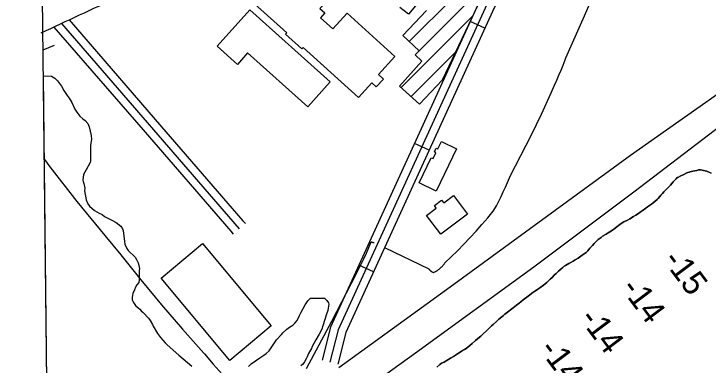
# Model space of a CAD drawing. Extents: x 3683613 to 3738215, y 469626 to 495384.
# Drawn here: x 3687652 to 3688948, y 487753 to 488409 of the extents above; entities that cross this region are included whole.
import ezdxf

# ---------------------------------------------------------------- set-up
doc = ezdxf.new("R2010")
doc.units = 0
for name, color, linetype in [('V-BLDG-OTLN', 7, 'Continuous'), ('V-GRID-FRAM', 7, 'Continuous'), ('V-LEVE-TOET', 7, 'Continuous'), ('V-ROAD-CNTR', 7, 'Continuous'), ('V-SITE-VEGE', 7, 'Continuous'), ('V-TOPO-SHOR', 7, 'Continuous'), ('V-TOPO-SPOT', 7, 'Continuous')]:
    doc.layers.add(name, color=color, linetype=linetype)

msp = doc.modelspace()

# ---------------------------------------------------------------- linework, layer by layer
at = {"layer": 'V-BLDG-OTLN'}
for p, q in [((3688390.1, 488357.4), (3688562.9, 488530.2)), ((3688408.3, 488340.2), (3688516.6, 488448.5)), ((3688374.8, 488271.4), (3688507.9, 488404.5)), ((3688393.3, 488254.6), (3688475.9, 488337.1))]:
    msp.add_line(p, q, dxfattribs=at)
for points in [[(3688363.3, 488329.6), (3688332.6, 488295.6), (3688341.7, 488287.3), (3688328.5, 488272.7), (3688320.2, 488280.2), (3688295.4, 488252.7), (3688191.8, 488346.2), (3688189.6, 488343.8), (3688159.2, 488371.3), (3688161.2, 488373.6), (3688101.1, 488427.8), (3688142.8, 488474), (3688151.4, 488466.2), (3688172.7, 488489.8), (3688235.8, 488432.8), (3688223.3, 488418.9), (3688232.2, 488410.9), (3688224, 488401.8), (3688247.3, 488380.8), (3688273.9, 488410.3)], [(3688242.3, 488282.4), (3688200.5, 488235.6), (3688088, 488336.1), (3688069, 488314.8), (3688031.3, 488348.5), (3688092.2, 488416.6)], [(3688440.3, 488078.3), (3688408.5, 488093.5), (3688431.1, 488140.6), (3688434.6, 488138.9), (3688439.9, 488149.8), (3688436.9, 488151.2), (3688440.4, 488158.3), (3688443.5, 488156.8), (3688450.2, 488170.7), (3688478.2, 488157.3)], [(3688448.9, 487997.6), (3688422.2, 488032.8), (3688440.4, 488046.6), (3688437, 488051.1), (3688450.4, 488061.2), (3688454.3, 488056.1), (3688472.5, 488069.9), (3688498.7, 488035.4)], [(3688004, 487980.1), (3688132.2, 487826.5), (3688054.7, 487761.8), (3687926.5, 487915.4)]]:
    msp.add_lwpolyline(points, close=True, dxfattribs=at)
for points in [[(3688525, 488440.4), (3688451.2, 488285.1), (3688409.2, 488240.2), (3688371.8, 488274.1), (3688413.7, 488320.5), (3688401, 488332.3), (3688408.3, 488340.1), (3688378.3, 488368.6), (3688422.4, 488415.2)], [(3688410.8, 488435.7), (3688388.7, 488408.7), (3688372.4, 488420.9)]]:
    msp.add_lwpolyline(points, dxfattribs=at)
at = {"layer": 'V-GRID-FRAM'}
msp.add_lwpolyline([(3687651.7, 493221.8), (3719350.3, 493590.7), (3719569.8, 475409.4), (3687855.3, 475040.3), (3687651.7, 493221.8)], dxfattribs=at)
at = {"layer": 'V-LEVE-TOET'}
for points in [[(3688258.5, 487748.9), (3688466.2, 487899.4), (3688803.1, 488145.2), (3689067.6, 488331.3)], [(3688996.3, 488218.7), (3688809.7, 488076.2), (3688622.7, 487936.2), (3688401.7, 487775.6), (3688274.9, 487684)]]:
    msp.add_lwpolyline(points, dxfattribs=at)
at = {"layer": 'V-ROAD-CNTR'}
for p, q in [((3688531.1, 488382.1), (3688503.8, 488394.6)), ((3688427.2, 488154.7), (3688399.9, 488167.2)), ((3688323.3, 487927.3), (3688296.1, 487939.8))]:
    msp.add_line(p, q, dxfattribs=at)
for points in [[(3688751.7, 488885.9), (3688531.8, 488419.8), (3688257.4, 487819.1), (3688242, 487759)], [(3688731.8, 488878.8), (3688518.2, 488426.1), (3688243.2, 487824.1), (3688227.5, 487762.7)], [(3688758.9, 488866), (3688545.4, 488413.5), (3688271.6, 487814.1), (3688256.5, 487755.3)], [(3687740.7, 488391), (3688072.7, 488007.7)], [(3687754.8, 488397.6), (3687915.7, 488211.9)], [(3687726.5, 488384.5), (3687893, 488192.3)], [(3687915.7, 488211.9), (3688079.4, 488022.9)], [(3687893, 488192.3), (3688056.7, 488003.3)], [(3688079.4, 488022.9), (3688084.1, 488017.6)], [(3688056.7, 488003.3), (3688061.4, 487997.9)]]:
    msp.add_lwpolyline(points, dxfattribs=at)
msp.add_spline([(3687702.9, 488373.5), (3687846.1, 488439.9), (3688068.4, 488539.2), (3688266.3, 488645.5), (3688507.8, 488813.9), (3688673, 488939.5)], degree=3, dxfattribs=at)
at = {"layer": 'V-SITE-VEGE'}
for p, q in [((3687706.9, 488292.7), (3687710.2, 488293.3)), ((3687714.7, 487596.9), (3687706.9, 488292.7)), ((3687710.2, 488293.3), (3687722.1, 488292.5)), ((3687722.1, 488292.5), (3687728.3, 488288.9)), ((3687728.3, 488288.9), (3687732.9, 488284.3)), ((3687732.9, 488284.3), (3687740.6, 488273.9)), ((3687740.6, 488273.9), (3687745.1, 488266.1)), ((3687745.1, 488266.1), (3687750.9, 488256.4)), ((3687750.9, 488256.4), (3687754.9, 488251.7)), ((3687754.9, 488251.7), (3687759.6, 488243.9)), ((3687759.6, 488243.9), (3687765.8, 488231.3)), ((3687765.8, 488231.3), (3687769.4, 488225.3)), ((3687769.4, 488225.3), (3687775, 488218.2)), ((3687775, 488218.2), (3687780.7, 488213.1)), ((3687780.7, 488213.1), (3687785, 488210)), ((3687785, 488210), (3687789.6, 488204.5)), ((3687789.6, 488204.5), (3687792.2, 488197.9)), ((3687792.2, 488197.9), (3687796.3, 488182.3)), ((3687796.3, 488182.3), (3687796.4, 488174.4)), ((3687795.1, 488167.4), (3687794.7, 488163.2)), ((3687795.9, 488171.5), (3687795.1, 488167.4)), ((3687796.4, 488174.4), (3687795.9, 488171.5)), ((3687794.7, 488163.2), (3687795, 488138.6)), ((3687794, 488131.8), (3687786.9, 488117.8)), ((3687794.6, 488134.2), (3687794, 488131.8)), ((3687795, 488138.6), (3687794.6, 488134.2)), ((3687786.9, 488117.8), (3687783.9, 488113.4)), ((3687781.8, 488108.9), (3687780.6, 488098.7)), ((3687783.9, 488113.4), (3687781.8, 488108.9)), ((3687780.6, 488098.7), (3687781, 488096.2)), ((3687781, 488096.2), (3687782.5, 488092.6)), ((3687782.5, 488092.6), (3687783.9, 488083.9)), ((3687783.9, 488083.9), (3687783.7, 488078.8)), ((3687783.7, 488078.8), (3687786.9, 488061.9)), ((3687786.9, 488061.9), (3687789.9, 488054.3)), ((3687789.9, 488054.3), (3687792.9, 488050.3)), ((3687792.9, 488050.3), (3687802.3, 488042.3)), ((3687802.3, 488042.3), (3687806.5, 488039.5)), ((3687806.5, 488039.5), (3687810.8, 488037.2)), ((3687810.8, 488037.2), (3687816.5, 488034.3)), ((3687816.5, 488034.3), (3687821.2, 488031.1)), ((3687821.2, 488031.1), (3687825.6, 488028.4)), ((3687825.6, 488028.4), (3687834.5, 488024.2)), ((3687834.5, 488024.2), (3687842.6, 488019.6)), ((3687842.6, 488019.6), (3687851.1, 488012.9)), ((3687851.1, 488012.9), (3687854.3, 488008)), ((3687854.3, 488008), (3687855.6, 488004.4)), ((3687855.6, 488004.4), (3687858, 487984.3)), ((3687858, 487984.3), (3687859.1, 487979.2)), ((3687859.1, 487979.2), (3687862.3, 487970.8)), ((3687862.3, 487970.8), (3687865.1, 487967.4)), ((3687865.1, 487967.4), (3687877.9, 487954.7)), ((3687877.9, 487954.7), (3687880.6, 487950.5)), ((3687880.6, 487950.5), (3687883.8, 487944.2)), ((3687883.8, 487944.2), (3687886.2, 487933.6)), ((3687886.2, 487933.6), (3687885.8, 487929.4)), ((3687885.8, 487929.4), (3687885.6, 487923.4)), ((3687885.6, 487923.4), (3687885.9, 487911.8)), ((3687884.9, 487907.3), (3687881.5, 487903.1)), ((3687885.9, 487911.8), (3687884.9, 487907.3)), ((3687879, 487898.6), (3687876.7, 487893.9)), ((3687881.5, 487903.1), (3687879, 487898.6)), ((3687872.9, 487883.3), (3687872.3, 487879.9)), ((3687874.1, 487887.2), (3687872.9, 487883.3)), ((3687876.7, 487893.9), (3687874.1, 487887.2)), ((3687872.3, 487879.9), (3687872.3, 487875.3)), ((3687872.3, 487875.3), (3687873.6, 487872.7)), ((3687873.6, 487872.7), (3687876.6, 487868.1)), ((3687876.6, 487868.1), (3687879.1, 487864.7)), ((3687879.1, 487864.7), (3687883.6, 487860.5)), ((3687883.6, 487860.5), (3687886.6, 487858)), ((3687886.6, 487858), (3687889.5, 487855)), ((3687889.5, 487855), (3687893.4, 487851.7)), ((3687893.4, 487851.7), (3687903, 487841.1)), ((3687903, 487841.1), (3687906.2, 487836.9)), ((3687906.2, 487836.9), (3687910.4, 487829.3)), ((3687910.4, 487829.3), (3687911.9, 487826.3)), ((3687911.9, 487826.3), (3687920, 487812.4)), ((3687920, 487812.4), (3687925.2, 487804.8)), ((3687925.2, 487804.8), (3687934.3, 487794.7)), ((3687934.3, 487794.7), (3687937.7, 487791.1)), ((3687937.7, 487791.1), (3687959.6, 487771.9)), ((3687959.6, 487771.9), (3687983.9, 487751.5))]:
    msp.add_line(p, q, dxfattribs=at)
msp.add_lwpolyline([(3688090, 487750.5), (3688095, 487755.6), (3688110.7, 487767.1), (3688118.3, 487772.2), (3688122.5, 487775.2), (3688128.2, 487780.3), (3688130.9, 487783.7), (3688142.1, 487800.7), (3688151.5, 487810.7), (3688154.1, 487813.7), (3688161.2, 487820.7), (3688166.1, 487824.3), (3688169.3, 487826.3), (3688172.4, 487828), (3688176.6, 487831.4), (3688180.6, 487836.9), (3688185.1, 487846), (3688188.2, 487852.2), (3688195.8, 487865.6), (3688200.8, 487873.2), (3688205.7, 487878.3), (3688231.5, 487878.2), (3688236.4, 487874.2), (3688239.2, 487869.6), (3688239.6, 487867), (3688238.8, 487859.6), (3688237.7, 487855.4), (3688235.2, 487848.2), (3688228.8, 487826.5), (3688226.5, 487820.2), (3688221.9, 487811.2), (3688215.8, 487800.4), (3688208.4, 487786.8), (3688207.2, 487784.1), (3688202.1, 487774.9), (3688199.2, 487768.8), (3688197.3, 487765.4), (3688194.6, 487759.4), (3688193.1, 487757.5), (3688190.4, 487754.3), (3688187.4, 487751.8)], dxfattribs=at)
at = {"layer": 'V-TOPO-SHOR'}
for points in [[(3688344.1, 487973.1), (3688426.5, 487932.8), (3688426.5, 487932.8), (3688426.9, 487932.3), (3688427.4, 487931.8), (3688427.9, 487931.3), (3688428.4, 487930.9), (3688428.9, 487930.4), (3688429.5, 487929.9), (3688430, 487929.5), (3688430.5, 487929), (3688431.1, 487928.6), (3688431.6, 487928.2), (3688432.2, 487927.8), (3688432.7, 487927.3), (3688433.3, 487927), (3688433.9, 487926.6), (3688434.5, 487926.2), (3688435, 487925.9), (3688435.8, 487926.3), (3688436.7, 487926.7), (3688437.5, 487927.2), (3688438.4, 487927.6), (3688439.2, 487928.1), (3688440.1, 487928.6), (3688440.9, 487929.1), (3688441.7, 487929.6), (3688442.5, 487930.2), (3688443.3, 487930.7), (3688444.1, 487931.3), (3688444.8, 487931.9), (3688445.6, 487932.5), (3688446.3, 487933.1), (3688447.1, 487933.7), (3688447.8, 487934.3), (3688448.5, 487935), (3688449.2, 487935.6), (3688449.9, 487936.3), (3688450.6, 487937), (3688451.3, 487937.6), (3688451.9, 487938.3), (3688452.6, 487939.1), (3688453.2, 487939.8), (3688453.8, 487940.5), (3688454.4, 487941.3), (3688455, 487942), (3688455.6, 487942.8), (3688456.2, 487943.6), (3688456.5, 487944), (3688468.5, 487955.4), (3688480.4, 487967), (3688492, 487978.9), (3688503.4, 487990.9), (3688514.7, 488003.2), (3688525.7, 488015.6), (3688536.5, 488028.2), (3688547, 488041), (3688548.2, 488042.5), (3688548.2, 488042.5), (3688552.8, 488050.9), (3688557.2, 488059.4), (3688561.6, 488068), (3688565.7, 488076.6), (3688569.7, 488085.4), (3688573.6, 488094.2), (3688577.3, 488103), (3688578.6, 488106.2), (3688598.7, 488144.5), (3688618.1, 488183.1), (3688636.8, 488222.1), (3688654.9, 488261.5), (3688661.2, 488275.8), (3688661.2, 488275.8), (3688665.5, 488285.1), (3688669.6, 488294.4), (3688673.6, 488303.9), (3688677.3, 488313.4), (3688681, 488323), (3688682.4, 488326.9), (3688682.4, 488326.9), (3688717.2, 488405.6), (3688730, 488433.7)], [(3687706.3, 488342.1), (3687727.8, 488350.7)], [(3687708.6, 488137), (3687718.8, 488123.6), (3687769.5, 488059), (3687821.4, 487995.2), (3687851.5, 487959.2), (3687851.5, 487959.2), (3687889, 487912.4), (3687927.3, 487866.2), (3687966.4, 487820.7), (3688006.2, 487775.9), (3688007.6, 487774.4), (3688007.6, 487774.4), (3688023.9, 487755.4), (3688040.5, 487736.7)], [(3688954.1, 488111.5), (3688945.8, 488115.3), (3688942.7, 488116.3), (3688934, 488117.7), (3688929.9, 488117.7), (3688926.8, 488116.6), (3688919.6, 488115.3), (3688914.9, 488114.3), (3688908.1, 488112.1), (3688902.7, 488109.5), (3688896.1, 488105.9), (3688891.7, 488103.8), (3688890.6, 488103.3), (3688888.7, 488101.4), (3688886, 488098.7), (3688882.8, 488095.3), (3688878.2, 488089.5), (3688875.2, 488086.5), (3688871.9, 488082.9), (3688869.1, 488080.4), (3688865.5, 488076.8), (3688863, 488073.8), (3688860, 488070.4), (3688858.2, 488068), (3688855, 488064.6), (3688852.9, 488062.3), (3688849.5, 488059.3), (3688845.5, 488056.1), (3688842.3, 488054), (3688834.9, 488048.9), (3688831.6, 488046.3), (3688824.8, 488041.6), (3688821.2, 488038.9), (3688818.1, 488036.5), (3688813.2, 488033.5), (3688808.6, 488030.5), (3688802.2, 488026.7), (3688797.6, 488024.1), (3688791, 488020.7), (3688786, 488017.9), (3688780.5, 488013.9), (3688777.9, 488011.8), (3688771.8, 488007.3), (3688767.8, 488004.1), (3688764.6, 488002.2), (3688761.5, 488000), (3688757.5, 487997.7), (3688751.1, 487993.8), (3688748.4, 487991.7), (3688742.7, 487987.7), (3688739.1, 487984), (3688735.3, 487980.2), (3688732.1, 487976.8), (3688730.2, 487974.5), (3688727.5, 487971.7), (3688723.5, 487966.8), (3688720.3, 487963.8), (3688716.5, 487960.8), (3688713.2, 487958.7), (3688705.3, 487953), (3688700.1, 487949.8), (3688696.3, 487947.6), (3688691.6, 487945.1), (3688687.8, 487943.1), (3688681.7, 487939.5), (3688679.2, 487937.8), (3688676.8, 487935.9)], [(3688767.8, 488004.1), (3688771.8, 488007.3), (3688777.9, 488011.8), (3688780.5, 488013.9), (3688786, 488017.9), (3688791, 488020.7), (3688797.6, 488024.1), (3688802.2, 488026.7), (3688808.6, 488030.5), (3688813.2, 488033.5), (3688818.1, 488036.5), (3688821.2, 488038.9), (3688824.8, 488041.6), (3688831.6, 488046.3), (3688834.9, 488048.9), (3688842.3, 488054), (3688845.5, 488056.1), (3688849.5, 488059.3), (3688852.9, 488062.3), (3688855, 488064.6), (3688858.2, 488068), (3688860, 488070.4), (3688863, 488073.8), (3688865.5, 488076.8), (3688869.1, 488080.4), (3688871.9, 488082.9), (3688875.2, 488086.5), (3688878.2, 488089.5), (3688882.8, 488095.3), (3688886, 488098.7), (3688888.7, 488101.4), (3688890.6, 488103.3), (3688891.7, 488103.8), (3688896.1, 488105.9), (3688902.7, 488109.5), (3688908.1, 488112.1), (3688914.9, 488114.3), (3688919.6, 488115.3), (3688926.8, 488116.6), (3688929.9, 488117.7), (3688934, 488117.7), (3688942.7, 488116.3), (3688945.8, 488115.3), (3688954.1, 488111.5)], [(3688441.7, 487749.7), (3688447, 487754.6), (3688450.4, 487756.7), (3688455, 487758.8), (3688458.9, 487761.2), (3688467.3, 487766.3), (3688472.6, 487769.5), (3688476.6, 487772.1), (3688480, 487774.4), (3688483.1, 487776.6), (3688489.7, 487780.4), (3688493.5, 487782.3), (3688496.2, 487784.2), (3688503.4, 487789.8), (3688507.8, 487793.6), (3688514, 487799.1), (3688517.5, 487802.3), (3688521.3, 487805.7), (3688523.7, 487807.7), (3688528.3, 487811.7), (3688534, 487817.5), (3688538, 487821.3), (3688540.3, 487823.4), (3688543.5, 487826.4), (3688546.6, 487829.2), (3688552.8, 487834.7), (3688557.6, 487839), (3688562.7, 487843.2), (3688566.3, 487846.2), (3688568.8, 487848.5), (3688576.2, 487854.1), (3688579.3, 487856.4), (3688584, 487860.3), (3688586.9, 487862.6), (3688590.1, 487865.2), (3688595, 487868.8), (3688598.3, 487871.8), (3688602.8, 487875.2), (3688611.8, 487881.8), (3688615.4, 487884.5), (3688621.1, 487889.2), (3688624.3, 487891.4), (3688627.7, 487893.3), (3688630, 487895.2), (3688634, 487897.8), (3688641, 487902.9), (3688647.1, 487907.8), (3688649.6, 487909.9), (3688653.2, 487913.5), (3688656.6, 487916.9), (3688661.2, 487921.6), (3688664.4, 487924.4), (3688669, 487928.9), (3688673.9, 487933.1), (3688676.8, 487935.9), (3688679.2, 487937.8), (3688681.7, 487939.5), (3688687.8, 487943.1), (3688691.6, 487945.1), (3688696.3, 487947.6), (3688700.1, 487949.8), (3688705.3, 487953), (3688713.2, 487958.7), (3688716.5, 487960.8), (3688720.3, 487963.8), (3688723.5, 487966.8), (3688727.5, 487971.7), (3688730.2, 487974.5), (3688732.1, 487976.8), (3688735.3, 487980.2), (3688739.1, 487984), (3688742.7, 487987.7), (3688748.4, 487991.7), (3688751.1, 487993.8), (3688757.5, 487997.7), (3688761.5, 488000), (3688764.6, 488002.2), (3688767.8, 488004.1)], [(3688198.2, 487747.1), (3688245.6, 487835.3), (3688291.4, 487924.4), (3688294.9, 487931.4), (3688300.1, 487941.6), (3688305.1, 487951.9), (3688309.9, 487962.3), (3688314.5, 487972.8), (3688319, 487983.4), (3688319.1, 487983.6), (3688319.1, 487983.6), (3688319.3, 487983.5), (3688319.4, 487983.4), (3688319.6, 487983.3), (3688319.8, 487983.2), (3688320, 487983.2), (3688320.2, 487983.1), (3688320.5, 487983), (3688320.7, 487982.9), (3688320.9, 487982.9), (3688321.1, 487982.8), (3688321.3, 487982.8), (3688321.5, 487982.7), (3688321.7, 487982.7), (3688321.9, 487982.6), (3688322.1, 487982.6), (3688322.3, 487982.5), (3688322.5, 487982.5), (3688322.8, 487982.5), (3688323, 487982.4), (3688323.2, 487982.4)], [(3688323.2, 487982.4), (3688323.4, 487982.4), (3688323.6, 487982.4), (3688323.8, 487982.4), (3688324, 487982.3), (3688324.3, 487982.3), (3688324.4, 487982.3)], [(3688676.8, 487935.9), (3688673.9, 487933.1), (3688669, 487928.9), (3688664.4, 487924.4), (3688661.2, 487921.6), (3688656.6, 487916.9), (3688653.2, 487913.5), (3688649.6, 487909.9), (3688647.1, 487907.8), (3688641, 487902.9), (3688634, 487897.8), (3688630, 487895.2), (3688627.7, 487893.3), (3688624.3, 487891.4), (3688621.1, 487889.2), (3688615.4, 487884.5), (3688611.8, 487881.8), (3688602.8, 487875.2), (3688598.3, 487871.8), (3688595, 487868.8), (3688590.1, 487865.2), (3688586.9, 487862.6), (3688584, 487860.3), (3688579.3, 487856.4), (3688576.2, 487854.1), (3688568.8, 487848.5), (3688566.3, 487846.2), (3688562.7, 487843.2), (3688557.6, 487839), (3688552.8, 487834.7), (3688546.6, 487829.2), (3688543.5, 487826.4), (3688540.3, 487823.4), (3688538, 487821.3), (3688534, 487817.5), (3688528.3, 487811.7), (3688523.7, 487807.7), (3688521.3, 487805.7), (3688517.5, 487802.3), (3688514, 487799.1), (3688507.8, 487793.6), (3688503.4, 487789.8), (3688496.2, 487784.2), (3688493.5, 487782.3), (3688489.7, 487780.4), (3688483.1, 487776.6), (3688480, 487774.4), (3688476.6, 487772.1), (3688472.6, 487769.5), (3688467.3, 487766.3), (3688458.9, 487761.2), (3688455, 487758.8), (3688450.4, 487756.7), (3688447, 487754.6), (3688441.7, 487749.7)]]:
    msp.add_lwpolyline(points, dxfattribs=at)

# ---------------------------------------------------------------- texts
at = {"layer": 'V-TOPO-SPOT'}
for s, p in [('-15', (3688862.3, 487949.2)), ('-14', (3688783.7, 487896.7)), ('-14', (3688706.3, 487840)), ('-14', (3688631.1, 487782.4))]:
    msp.add_text(s, height=45, rotation=306.9347, dxfattribs=at).set_placement(p)

doc.saveas('drawing.dxf')
